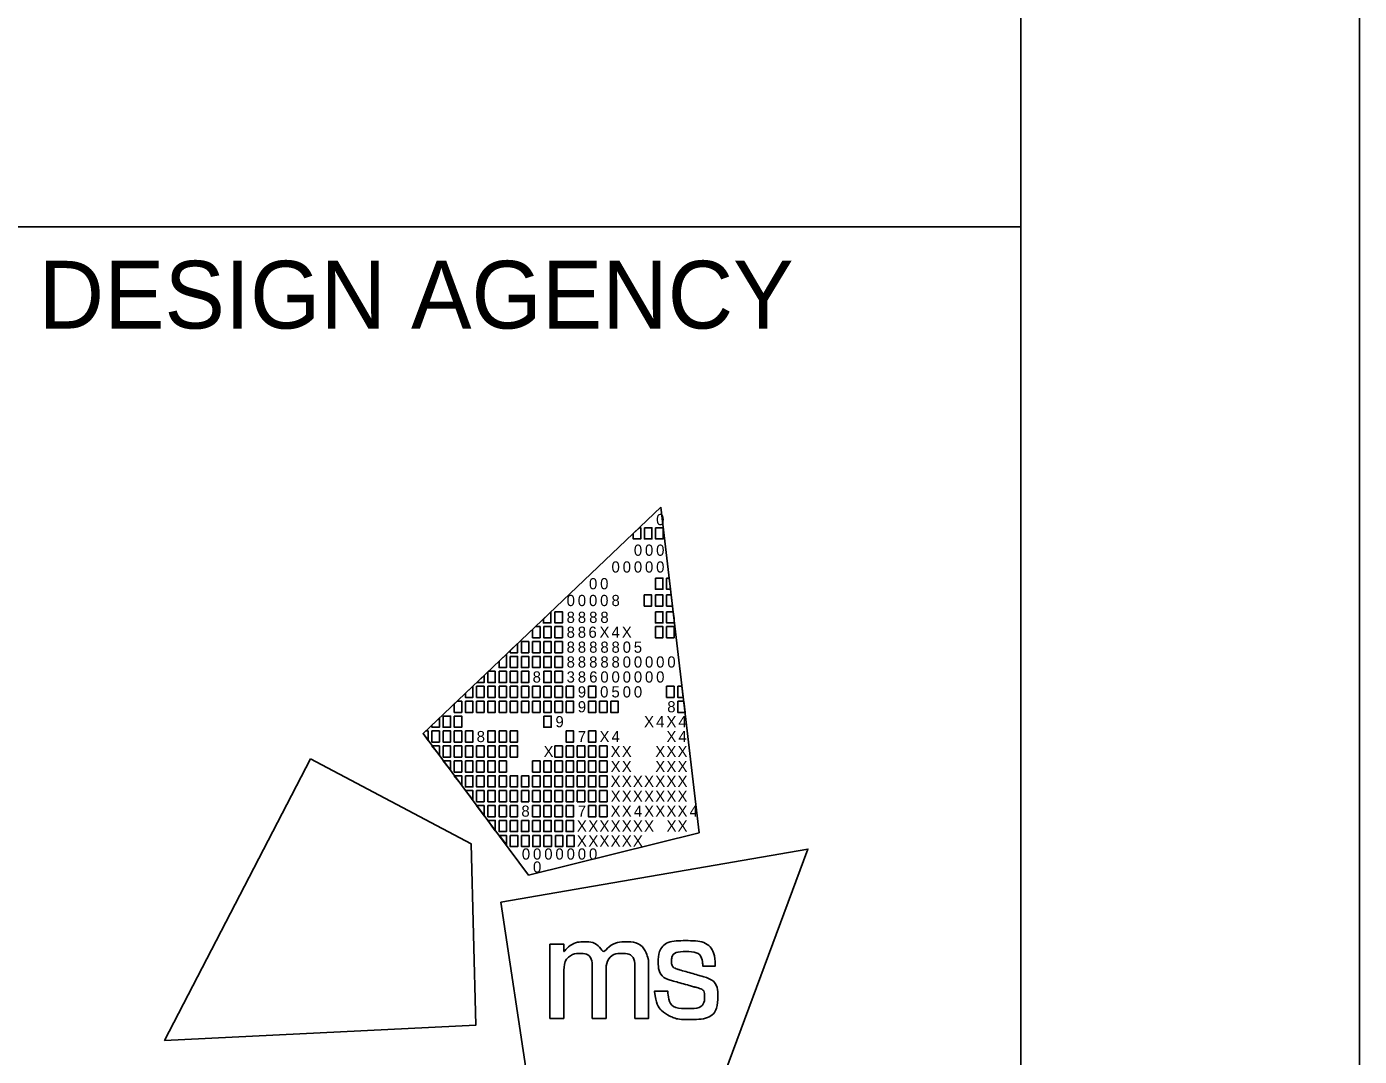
# Model space of a CAD drawing. Extents: x 0 to 34, y 0 to 22.
# Drawn here: x 32.032 to 34, y 3.275 to 4.796 of the extents above; entities that cross this region are included whole.
import ezdxf

# ---------------------------------------------------------------- set-up
doc = ezdxf.new("R2010")
doc.units = 0
for name, color, linetype in [('SH_Border', 7, 'Continuous'), ('SH_Cut_Line', 7, 'Continuous'), ('SH_Data', 7, 'Continuous')]:
    doc.layers.add(name, color=color, linetype=linetype)

msp = doc.modelspace()

# ---------------------------------------------------------------- linework, layer by layer
at = {"layer": 'SH_Border'}
for p, q in [((32, 4.5), (33.5, 4.5)), ((32.6175, 3.7519), (32.9688, 4.0861)), ((32.9688, 4.0861), (32.9688, 4.0861)), ((32.9688, 4.0861), (33.0253, 3.6052)), ((32.773, 3.543), (32.6175, 3.7519)), ((33.0253, 3.6052), (32.773, 3.543))]:
    msp.add_line(p, q, dxfattribs=at)
for points in [[(1.5, 21.5), (33.5, 21.5), (33.5, 0.5), (1.5, 0.5)], [(32.9279, 4.0472), (32.9369, 4.0558), (32.9389, 4.0558), (32.9389, 4.0393), (32.9279, 4.0393)], [(32.9444, 4.0558), (32.9554, 4.0558), (32.9554, 4.0393), (32.9444, 4.0393)], [(32.9609, 4.0558), (32.9719, 4.0558), (32.9719, 4.0393), (32.9609, 4.0393)], [(32.9606, 3.9815), (32.9716, 3.9815), (32.9716, 3.965), (32.9606, 3.965)], [(32.9771, 3.9815), (32.9811, 3.9815), (32.983, 3.965), (32.9771, 3.965)], [(32.9441, 3.9567), (32.9551, 3.9567), (32.9551, 3.9402), (32.9441, 3.9402)], [(32.9606, 3.9567), (32.9716, 3.9567), (32.9716, 3.9402), (32.9606, 3.9402)], [(32.9771, 3.9567), (32.984, 3.9567), (32.9859, 3.9402), (32.9771, 3.9402)], [(32.7953, 3.9211), (32.8064, 3.9316), (32.8064, 3.9154), (32.7953, 3.9154)], [(32.8123, 3.9319), (32.8233, 3.9319), (32.8233, 3.9154), (32.8123, 3.9154)], [(32.9606, 3.9319), (32.9716, 3.9319), (32.9716, 3.9154), (32.9606, 3.9154)], [(32.9771, 3.9319), (32.9869, 3.9319), (32.9881, 3.9218), (32.9881, 3.9154), (32.9771, 3.9154)], [(32.7958, 3.9099), (32.8068, 3.9099), (32.8068, 3.8934), (32.7958, 3.8934)], [(32.8123, 3.9099), (32.8233, 3.9099), (32.8233, 3.8934), (32.8123, 3.8934)], [(32.9606, 3.9099), (32.9716, 3.9099), (32.9716, 3.8934), (32.9606, 3.8934)], [(32.9771, 3.9099), (32.9881, 3.9099), (32.9881, 3.8934), (32.9771, 3.8934)], [(32.7627, 3.8879), (32.7737, 3.8879), (32.7737, 3.8714), (32.7627, 3.8714)], [(32.7793, 3.8879), (32.7903, 3.8879), (32.7903, 3.8714), (32.7793, 3.8714)], [(32.7958, 3.8879), (32.8068, 3.8879), (32.8068, 3.8714), (32.7958, 3.8714)], [(32.8123, 3.8879), (32.8233, 3.8879), (32.8233, 3.8714), (32.8123, 3.8714)], [(32.7462, 3.8659), (32.7572, 3.8659), (32.7572, 3.8494), (32.7462, 3.8494)], [(32.7627, 3.8659), (32.7737, 3.8659), (32.7737, 3.8494), (32.7627, 3.8494)], [(32.7793, 3.8659), (32.7903, 3.8659), (32.7903, 3.8494), (32.7793, 3.8494)], [(32.7958, 3.8659), (32.8068, 3.8659), (32.8068, 3.8494), (32.7958, 3.8494)], [(32.8123, 3.8659), (32.8233, 3.8659), (32.8233, 3.8494), (32.8123, 3.8494)], [(32.7297, 3.8439), (32.7407, 3.8439), (32.7407, 3.8273), (32.7297, 3.8273)], [(32.7462, 3.8439), (32.7572, 3.8439), (32.7572, 3.8273), (32.7462, 3.8273)], [(32.7627, 3.8439), (32.7737, 3.8439), (32.7737, 3.8273), (32.7627, 3.8273)], [(32.7958, 3.8439), (32.8068, 3.8439), (32.8068, 3.8273), (32.7958, 3.8273)], [(32.8123, 3.8439), (32.8233, 3.8439), (32.8233, 3.8273), (32.8123, 3.8273)], [(32.6967, 3.8218), (32.7077, 3.8218), (32.7077, 3.8053), (32.6967, 3.8053)], [(32.7132, 3.8218), (32.7242, 3.8218), (32.7242, 3.8053), (32.7132, 3.8053)], [(32.7297, 3.8218), (32.7407, 3.8218), (32.7407, 3.8053), (32.7297, 3.8053)], [(32.7462, 3.8218), (32.7572, 3.8218), (32.7572, 3.8053), (32.7462, 3.8053)], [(32.7627, 3.8218), (32.7737, 3.8218), (32.7737, 3.8053), (32.7627, 3.8053)], [(32.7793, 3.8218), (32.7903, 3.8218), (32.7903, 3.8053), (32.7793, 3.8053)], [(32.7958, 3.8218), (32.8068, 3.8218), (32.8068, 3.8053), (32.7958, 3.8053)], [(32.8123, 3.8218), (32.8233, 3.8218), (32.8233, 3.8053), (32.8123, 3.8053)], [(32.8288, 3.8218), (32.8398, 3.8218), (32.8398, 3.8053), (32.8288, 3.8053)], [(32.8618, 3.8218), (32.8728, 3.8218), (32.8728, 3.8053), (32.8618, 3.8053)], [(32.9771, 3.8218), (32.9881, 3.8218), (32.9881, 3.8053), (32.9771, 3.8053)], [(32.9935, 3.8218), (32.9998, 3.8218), (33.0018, 3.8053), (32.9935, 3.8053)], [(32.6802, 3.7998), (32.6912, 3.7998), (32.6912, 3.7833), (32.6802, 3.7833)], [(32.6967, 3.7998), (32.7077, 3.7998), (32.7077, 3.7833), (32.6967, 3.7833)], [(32.7132, 3.7998), (32.7242, 3.7998), (32.7242, 3.7833), (32.7132, 3.7833)], [(32.7297, 3.7998), (32.7407, 3.7998), (32.7407, 3.7833), (32.7297, 3.7833)], [(32.7462, 3.7998), (32.7572, 3.7998), (32.7572, 3.7833), (32.7462, 3.7833)], [(32.7627, 3.7998), (32.7737, 3.7998), (32.7737, 3.7833), (32.7627, 3.7833)], [(32.7793, 3.7998), (32.7903, 3.7998), (32.7903, 3.7833), (32.7793, 3.7833)], [(32.7958, 3.7998), (32.8068, 3.7998), (32.8068, 3.7833), (32.7958, 3.7833)], [(32.8123, 3.7998), (32.8233, 3.7998), (32.8233, 3.7833), (32.8123, 3.7833)], [(32.8288, 3.7998), (32.8398, 3.7998), (32.8398, 3.7833), (32.8288, 3.7833)], [(32.8618, 3.7998), (32.8728, 3.7998), (32.8728, 3.7833), (32.8618, 3.7833)], [(32.8783, 3.7998), (32.8893, 3.7998), (32.8893, 3.7833), (32.8783, 3.7833)], [(32.8947, 3.7998), (32.9057, 3.7998), (32.9057, 3.7833), (32.8947, 3.7833)], [(32.9935, 3.7998), (33.0024, 3.7998), (33.0044, 3.7833), (32.9935, 3.7833)], [(32.6471, 3.7778), (32.6581, 3.7778), (32.6581, 3.7613), (32.6471, 3.7613)], [(32.6637, 3.7778), (32.6747, 3.7778), (32.6747, 3.7613), (32.6637, 3.7613)], [(32.7958, 3.7778), (32.8068, 3.7778), (32.8068, 3.7613), (32.7958, 3.7613)], [(32.6306, 3.7558), (32.6416, 3.7558), (32.6416, 3.7393), (32.6306, 3.7393)], [(32.6471, 3.7558), (32.6581, 3.7558), (32.6581, 3.7393), (32.6471, 3.7393)], [(32.6637, 3.7558), (32.6747, 3.7558), (32.6747, 3.7393), (32.6637, 3.7393)], [(32.6802, 3.7558), (32.6912, 3.7558), (32.6912, 3.7393), (32.6802, 3.7393)], [(32.7132, 3.7558), (32.7242, 3.7558), (32.7242, 3.7393), (32.7132, 3.7393)], [(32.7297, 3.7558), (32.7407, 3.7558), (32.7407, 3.7393), (32.7297, 3.7393)], [(32.7462, 3.7558), (32.7572, 3.7558), (32.7572, 3.7393), (32.7462, 3.7393)], [(32.8288, 3.7558), (32.8398, 3.7558), (32.8398, 3.7393), (32.8288, 3.7393)], [(32.8618, 3.7558), (32.8728, 3.7558), (32.8728, 3.7393), (32.8618, 3.7393)], [(32.6306, 3.7338), (32.6416, 3.7338), (32.6416, 3.72)], [(32.6471, 3.7338), (32.6581, 3.7338), (32.6581, 3.7173), (32.6471, 3.7173)], [(32.6637, 3.7338), (32.6747, 3.7338), (32.6747, 3.7173), (32.6637, 3.7173)], [(32.6802, 3.7338), (32.6912, 3.7338), (32.6912, 3.7173), (32.6802, 3.7173)], [(32.6967, 3.7338), (32.7077, 3.7338), (32.7077, 3.7173), (32.6967, 3.7173)], [(32.7132, 3.7338), (32.7242, 3.7338), (32.7242, 3.7173), (32.7132, 3.7173)], [(32.7297, 3.7338), (32.7407, 3.7338), (32.7407, 3.7173), (32.7297, 3.7173)], [(32.7462, 3.7338), (32.7572, 3.7338), (32.7572, 3.7173), (32.7462, 3.7173)], [(32.8123, 3.7338), (32.8233, 3.7338), (32.8233, 3.7173), (32.8123, 3.7173)], [(32.8288, 3.7338), (32.8398, 3.7338), (32.8398, 3.7173), (32.8288, 3.7173)], [(32.8453, 3.7338), (32.8563, 3.7338), (32.8563, 3.7173), (32.8453, 3.7173)], [(32.8618, 3.7338), (32.8728, 3.7338), (32.8728, 3.7173), (32.8618, 3.7173)], [(32.8783, 3.7338), (32.8893, 3.7338), (32.8893, 3.7173), (32.8783, 3.7173)], [(32.6471, 3.7117), (32.6581, 3.7117), (32.6581, 3.698)], [(32.6637, 3.7117), (32.6747, 3.7117), (32.6747, 3.6952), (32.6637, 3.6952)], [(32.6802, 3.7117), (32.6912, 3.7117), (32.6912, 3.6952), (32.6802, 3.6952)], [(32.6967, 3.7117), (32.7077, 3.7117), (32.7077, 3.6952), (32.6967, 3.6952)], [(32.7132, 3.7117), (32.7242, 3.7117), (32.7242, 3.6952), (32.7132, 3.6952)], [(32.7297, 3.7117), (32.7407, 3.7117), (32.7407, 3.6952), (32.7297, 3.6952)], [(32.7793, 3.7117), (32.7903, 3.7117), (32.7903, 3.6952), (32.7793, 3.6952)], [(32.7958, 3.7117), (32.8068, 3.7117), (32.8068, 3.6952), (32.7958, 3.6952)], [(32.8123, 3.7117), (32.8233, 3.7117), (32.8233, 3.6952), (32.8123, 3.6952)], [(32.8288, 3.7117), (32.8398, 3.7117), (32.8398, 3.6952), (32.8288, 3.6952)], [(32.8453, 3.7117), (32.8563, 3.7117), (32.8563, 3.6952), (32.8453, 3.6952)], [(32.8618, 3.7117), (32.8728, 3.7117), (32.8728, 3.6952), (32.8618, 3.6952)], [(32.8783, 3.7117), (32.8893, 3.7117), (32.8893, 3.6952), (32.8783, 3.6952)], [(32.6637, 3.6897), (32.6747, 3.6897), (32.6747, 3.676)], [(32.6747, 3.6897), (32.6747, 3.6897), (32.6747, 3.6897)], [(32.6802, 3.6897), (32.6912, 3.6897), (32.6912, 3.6732), (32.6802, 3.6732)], [(32.6967, 3.6897), (32.7077, 3.6897), (32.7077, 3.6732), (32.6967, 3.6732)], [(32.7132, 3.6897), (32.7242, 3.6897), (32.7242, 3.6732), (32.7132, 3.6732)], [(32.7297, 3.6897), (32.7407, 3.6897), (32.7407, 3.6732), (32.7297, 3.6732)], [(32.7462, 3.6897), (32.7572, 3.6897), (32.7572, 3.6732), (32.7462, 3.6732)], [(32.7627, 3.6897), (32.7737, 3.6897), (32.7737, 3.6732), (32.7627, 3.6732)], [(32.7793, 3.6897), (32.7903, 3.6897), (32.7903, 3.6732), (32.7793, 3.6732)], [(32.7958, 3.6897), (32.8068, 3.6897), (32.8068, 3.6732), (32.7958, 3.6732)], [(32.8123, 3.6897), (32.8233, 3.6897), (32.8233, 3.6732), (32.8123, 3.6732)], [(32.8288, 3.6897), (32.8398, 3.6897), (32.8398, 3.6732), (32.8288, 3.6732)], [(32.8453, 3.6897), (32.8563, 3.6897), (32.8563, 3.6732), (32.8453, 3.6732)], [(32.8618, 3.6897), (32.8728, 3.6897), (32.8728, 3.6732), (32.8618, 3.6732)], [(32.8783, 3.6897), (32.8893, 3.6897), (32.8893, 3.6732), (32.8783, 3.6732)], [(32.6802, 3.6677), (32.6912, 3.6677), (32.6912, 3.654)], [(32.6967, 3.6677), (32.7077, 3.6677), (32.7077, 3.6512), (32.6967, 3.6512)], [(32.7132, 3.6677), (32.7242, 3.6677), (32.7242, 3.6512), (32.7132, 3.6512)], [(32.7297, 3.6677), (32.7407, 3.6677), (32.7407, 3.6512), (32.7297, 3.6512)], [(32.7462, 3.6677), (32.7572, 3.6677), (32.7572, 3.6512), (32.7462, 3.6512)], [(32.7627, 3.6677), (32.7737, 3.6677), (32.7737, 3.6512), (32.7627, 3.6512)], [(32.7793, 3.6677), (32.7903, 3.6677), (32.7903, 3.6512), (32.7793, 3.6512)], [(32.7958, 3.6677), (32.8068, 3.6677), (32.8068, 3.6512), (32.7958, 3.6512)], [(32.8123, 3.6677), (32.8233, 3.6677), (32.8233, 3.6512), (32.8123, 3.6512)], [(32.8288, 3.6677), (32.8398, 3.6677), (32.8398, 3.6512), (32.8288, 3.6512)], [(32.8453, 3.6677), (32.8563, 3.6677), (32.8563, 3.6512), (32.8453, 3.6512)], [(32.8618, 3.6677), (32.8728, 3.6677), (32.8728, 3.6512), (32.8618, 3.6512)], [(32.8783, 3.6677), (32.8893, 3.6677), (32.8893, 3.6512), (32.8783, 3.6512)], [(32.7077, 3.6305), (32.6965, 3.6457), (32.7077, 3.6457)], [(32.7132, 3.6457), (32.7242, 3.6457), (32.7242, 3.6292), (32.7132, 3.6292)], [(32.7297, 3.6457), (32.7407, 3.6457), (32.7407, 3.6292), (32.7297, 3.6292)], [(32.7462, 3.6457), (32.7572, 3.6457), (32.7572, 3.6292), (32.7462, 3.6292)], [(32.7793, 3.6457), (32.7903, 3.6457), (32.7903, 3.6292), (32.7793, 3.6292)], [(32.7958, 3.6457), (32.8068, 3.6457), (32.8068, 3.6292), (32.7958, 3.6292)], [(32.8123, 3.6457), (32.8233, 3.6457), (32.8233, 3.6292), (32.8123, 3.6292)], [(32.8288, 3.6457), (32.8398, 3.6457), (32.8398, 3.6292), (32.8288, 3.6292)], [(32.8618, 3.6457), (32.8728, 3.6457), (32.8728, 3.6292), (32.8618, 3.6292)], [(32.8783, 3.6457), (32.8893, 3.6457), (32.8893, 3.6292), (32.8783, 3.6292)], [(32.724, 3.6082), (32.7132, 3.6237), (32.7242, 3.6237)], [(32.7297, 3.6237), (32.7407, 3.6237), (32.7407, 3.6072), (32.7297, 3.6072)], [(32.7462, 3.6237), (32.7572, 3.6237), (32.7572, 3.6072), (32.7462, 3.6072)], [(32.7627, 3.6237), (32.7737, 3.6237), (32.7737, 3.6072), (32.7627, 3.6072)], [(32.7793, 3.6237), (32.7903, 3.6237), (32.7903, 3.6072), (32.7793, 3.6072)], [(32.7958, 3.6237), (32.8068, 3.6237), (32.8068, 3.6072), (32.7958, 3.6072)], [(32.8123, 3.6237), (32.8233, 3.6237), (32.8233, 3.6072), (32.8123, 3.6072)], [(32.8288, 3.6237), (32.8398, 3.6237), (32.8398, 3.6072), (32.8288, 3.6072)], [(32.7302, 3.6017), (32.7407, 3.6017), (32.7408, 3.5875)], [(32.7463, 3.6017), (32.7573, 3.6017), (32.7573, 3.5852), (32.7463, 3.5852)], [(32.763, 3.6017), (32.774, 3.6017), (32.774, 3.5852), (32.763, 3.5852)], [(32.7794, 3.6017), (32.7904, 3.6017), (32.7904, 3.5852), (32.7794, 3.5852)], [(32.796, 3.6017), (32.807, 3.6017), (32.807, 3.5852), (32.796, 3.5852)], [(32.8129, 3.6017), (32.8239, 3.6017), (32.8239, 3.5851), (32.8129, 3.5851)], [(32.8296, 3.6017), (32.8406, 3.6017), (32.8406, 3.5851), (32.8296, 3.5851)]]:
    msp.add_lwpolyline(points, close=True, dxfattribs=at)
for points in [[(32.7903, 3.9099), (32.7836, 3.9099), (32.7793, 3.9058), (32.7793, 3.8934), (32.7903, 3.8934), (32.7903, 3.9099)], [(32.7572, 3.8849), (32.7462, 3.8744), (32.7462, 3.8714), (32.7572, 3.8714), (32.7572, 3.8849)], [(32.7407, 3.8691), (32.7297, 3.8587), (32.7297, 3.8494), (32.7407, 3.8494), (32.7407, 3.8691)], [(32.7077, 3.8377), (32.6968, 3.8273), (32.7077, 3.8273), (32.7077, 3.8377)], [(32.7242, 3.8439), (32.7141, 3.8439), (32.7132, 3.843), (32.7132, 3.8273), (32.7242, 3.8273), (32.7242, 3.8439)], [(32.6912, 3.822), (32.6802, 3.8115), (32.6802, 3.8053), (32.6912, 3.8053), (32.6912, 3.822)], [(32.6747, 3.7998), (32.6679, 3.7998), (32.6637, 3.7958), (32.6637, 3.7833), (32.6747, 3.7833), (32.6747, 3.7998)], [(32.6416, 3.7749), (32.6306, 3.7644), (32.6306, 3.7613), (32.6416, 3.7613), (32.6416, 3.7749)], [(32.6251, 3.7558), (32.6216, 3.7558), (32.6175, 3.7519), (32.6251, 3.7417), (32.6251, 3.7558)], [(32.4512, 3.7149), (32.2359, 3.2988), (32.6956, 3.3215), (32.6884, 3.5892), (32.4512, 3.7149)], [(33.0229, 3.1422), (33.1859, 3.5814), (32.7324, 3.5029), (32.7722, 3.2381), (33.0229, 3.1422)]]:
    msp.add_lwpolyline(points, dxfattribs=at)
for points in [[(32.8048, 3.3315), (32.8048, 3.3315), (32.8048, 3.4409), (32.8048, 3.4409), (32.8048, 3.4409), (32.8255, 3.4409), (32.8255, 3.4409), (32.8255, 3.4409), (32.8255, 3.4297), (32.8255, 3.4297), (32.8346, 3.4399), (32.8457, 3.4445), (32.8555, 3.4445), (32.8688, 3.4445), (32.8791, 3.4372), (32.8837, 3.4266), (32.8915, 3.4381), (32.905, 3.4446), (32.9166, 3.4446), (32.9325, 3.4446), (32.9451, 3.435), (32.9494, 3.4213), (32.9494, 3.4212), (32.9494, 3.4212), (32.9494, 3.4212), (32.9501, 3.419), (32.9506, 3.4172), (32.9506, 3.4071), (32.9506, 3.4071), (32.9506, 3.3314), (32.9506, 3.3314), (32.9506, 3.3314), (32.9303, 3.3314), (32.9303, 3.3314), (32.9303, 3.3314), (32.9303, 3.4048), (32.9303, 3.4048), (32.9303, 3.4201), (32.9219, 3.4274), (32.911, 3.4274), (32.8995, 3.4274), (32.8879, 3.4171), (32.8879, 3.4001), (32.8879, 3.4001), (32.8879, 3.3315), (32.8879, 3.3315), (32.8879, 3.3315), (32.8674, 3.3315), (32.8674, 3.3315), (32.8674, 3.3315), (32.8674, 3.4059), (32.8674, 3.4059), (32.8674, 3.4203), (32.8588, 3.4274), (32.8496, 3.4274), (32.8384, 3.4274), (32.8254, 3.417), (32.8254, 3.3962), (32.8254, 3.3962), (32.8254, 3.3315), (32.8254, 3.3315), (32.8254, 3.3315), (32.8048, 3.3315), (32.8048, 3.3315)], [(32.9595, 3.3709), (32.9595, 3.3709), (32.9595, 3.3717), (32.9595, 3.3717), (32.9595, 3.3717), (32.9603, 3.3717), (32.9603, 3.3717), (32.9603, 3.3717), (32.9783, 3.3717), (32.9783, 3.3717), (32.9783, 3.3717), (32.9789, 3.3717), (32.9789, 3.3717), (32.9789, 3.3717), (32.979, 3.371), (32.979, 3.371), (32.9803, 3.3554), (32.9887, 3.346), (33.009, 3.346), (33.0273, 3.346), (33.0333, 3.3554), (33.0333, 3.3631), (33.0333, 3.3732), (33.0256, 3.3758), (33.0175, 3.378), (33.0175, 3.378), (32.987, 3.3867), (32.987, 3.3867), (32.972, 3.3909), (32.9648, 3.4019), (32.9648, 3.4142), (32.9648, 3.4303), (32.9768, 3.4462), (33.0052, 3.4462), (33.0348, 3.4462), (33.0489, 3.4285), (33.0489, 3.4095), (33.0489, 3.4095), (33.0489, 3.4087), (33.0489, 3.4087), (33.0489, 3.4087), (33.0482, 3.4087), (33.0482, 3.4087), (33.0482, 3.4087), (33.0312, 3.4087), (33.0312, 3.4087), (33.0312, 3.4087), (33.0305, 3.4087), (33.0305, 3.4087), (33.0305, 3.4087), (33.0305, 3.4094), (33.0305, 3.4094), (33.0301, 3.4208), (33.0226, 3.43), (33.0056, 3.43), (32.9891, 3.43), (32.9843, 3.4218), (32.9843, 3.4157), (32.9843, 3.4108), (32.9869, 3.4059), (32.9959, 3.4033), (32.9959, 3.4033), (33.0255, 3.3948), (33.0255, 3.3948), (33.0462, 3.3889), (33.0527, 3.3777), (33.0527, 3.3639), (33.0527, 3.3462), (33.041, 3.3298), (33.0087, 3.3298), (32.9952, 3.3298), (32.9877, 3.3321), (32.9823, 3.3348), (32.969, 3.3414), (32.9609, 3.3536), (32.9595, 3.3709)]]:
    msp.add_open_spline(points, degree=3, dxfattribs=at)
at = {"layer": 'SH_Cut_Line'}
msp.add_lwpolyline([(0, 0), (34, 0), (34, 22), (0, 22)], close=True, dxfattribs=at)
at = {"layer": 'SH_Data'}
msp.add_line((32.75, 3.5), (32.75, 3.5), dxfattribs=at)

# ---------------------------------------------------------------- texts
at = {"layer": 'SH_Border'}
for s, p in [('0', (32.9617, 4.0597)), ('0', (32.9288, 4.0145)), ('0', (32.9452, 4.0145)), ('0', (32.9617, 4.0145)), ('0', (32.8958, 3.9897)), ('0', (32.9123, 3.9897)), ('0', (32.9288, 3.9897)), ('0', (32.9452, 3.9897)), ('0', (32.9617, 3.9897)), ('0', (32.8625, 3.965)), ('0', (32.879, 3.965)), ('0', (32.8295, 3.9402)), ('0', (32.846, 3.9402)), ('0', (32.8625, 3.9402)), ('0', (32.879, 3.9402)), ('8', (32.8958, 3.9402)), ('8', (32.8295, 3.9154)), ('8', (32.846, 3.9154)), ('8', (32.8628, 3.9154)), ('8', (32.8793, 3.9154)), ('8', (32.8295, 3.8934)), ('8', (32.846, 3.8934)), ('6', (32.8618, 3.8934)), ('X', (32.8781, 3.8934)), ('4', (32.8958, 3.8934)), ('X', (32.911, 3.8934)), ('8', (32.8295, 3.8713)), ('8', (32.846, 3.8713)), ('8', (32.8628, 3.8713)), ('8', (32.8794, 3.8713)), ('8', (32.8958, 3.8713)), ('0', (32.9123, 3.8713)), ('5', (32.9287, 3.8713)), ('8', (32.8295, 3.8494)), ('8', (32.846, 3.8494)), ('8', (32.8628, 3.8494)), ('8', (32.8794, 3.8494)), ('8', (32.8958, 3.8494)), ('0', (32.9123, 3.8494)), ('0', (32.9288, 3.8494)), ('0', (32.9452, 3.8494)), ('0', (32.9617, 3.8494)), ('0', (32.9782, 3.8494)), ('8', (32.7793, 3.8273)), ('3', (32.8295, 3.8273)), ('8', (32.846, 3.8273)), ('6', (32.8629, 3.8273)), ('0', (32.8793, 3.8273)), ('0', (32.8958, 3.8273)), ('0', (32.9123, 3.8273)), ('0', (32.9288, 3.8273)), ('0', (32.9452, 3.8273)), ('0', (32.9617, 3.8273)), ('9', (32.846, 3.8053)), ('0', (32.879, 3.8053)), ('5', (32.8957, 3.8053)), ('0', (32.9123, 3.8053)), ('0', (32.9288, 3.8053)), ('9', (32.846, 3.7833)), ('8', (32.9781, 3.7833)), ('9', (32.813, 3.7613)), ('X', (32.9439, 3.7613)), ('4', (32.9617, 3.7613)), ('X', (32.9769, 3.7613)), ('4', (32.9946, 3.7613)), ('8', (32.6967, 3.7393)), ('7', (32.846, 3.7393)), ('X', (32.8781, 3.7393)), ('4', (32.8958, 3.7393)), ('X', (32.9769, 3.7393)), ('4', (32.9946, 3.7393)), ('X', (32.7955, 3.7173)), ('X', (32.8945, 3.7173)), ('X', (32.911, 3.7173)), ('X', (32.9604, 3.7173)), ('X', (32.9769, 3.7173)), ('X', (32.9933, 3.7173)), ('X', (32.8945, 3.6952)), ('X', (32.911, 3.6952)), ('X', (32.9604, 3.6952)), ('X', (32.9769, 3.6952)), ('X', (32.9933, 3.6952)), ('X', (32.8945, 3.6732)), ('X', (32.911, 3.6732)), ('X', (32.9274, 3.6732)), ('X', (32.9439, 3.6732)), ('X', (32.9604, 3.6732)), ('X', (32.9769, 3.6732)), ('X', (32.9933, 3.6732)), ('X', (32.8945, 3.6512)), ('X', (32.911, 3.6512)), ('X', (32.9274, 3.6512)), ('X', (32.9439, 3.6512)), ('X', (32.9604, 3.6512)), ('X', (32.9769, 3.6512)), ('X', (32.9933, 3.6512)), ('8', (32.7627, 3.6292)), ('7', (32.846, 3.6292)), ('X', (32.8945, 3.6292)), ('X', (32.911, 3.6292)), ('4', (32.9288, 3.6292)), ('X', (32.9439, 3.6292)), ('X', (32.9604, 3.6292)), ('X', (32.9769, 3.6292)), ('X', (32.9933, 3.6292)), ('4', (33.0111, 3.6292)), ('X', (32.8447, 3.6072)), ('X', (32.8616, 3.6072)), ('X', (32.878, 3.6072)), ('X', (32.8945, 3.6072)), ('X', (32.911, 3.6072)), ('X', (32.9274, 3.6072)), ('X', (32.9439, 3.6072)), ('X', (32.9771, 3.6072)), ('X', (32.9933, 3.6072)), ('X', (32.8447, 3.5851)), ('X', (32.8616, 3.5851)), ('X', (32.878, 3.5851)), ('X', (32.8945, 3.5851)), ('X', (32.911, 3.5851)), ('X', (32.9274, 3.5851)), ('0', (32.7634, 3.5659)), ('0', (32.7799, 3.5659)), ('0', (32.7965, 3.5659)), ('0', (32.813, 3.5659)), ('0', (32.8295, 3.5659)), ('0', (32.846, 3.5659)), ('0', (32.8625, 3.5659)), ('0', (32.7799, 3.5467))]:
    msp.add_text(s, height=0.0165, rotation=360, dxfattribs=at).set_placement(p)
at = {"layer": 'SH_Data'}
msp.add_text('DESIGN AGENCY', height=0.1, dxfattribs=at).set_placement((32.05, 4.35))

doc.saveas('drawing.dxf')
